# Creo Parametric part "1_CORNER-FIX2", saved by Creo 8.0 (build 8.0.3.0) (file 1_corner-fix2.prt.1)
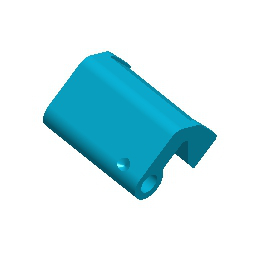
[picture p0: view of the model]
Units: millimeter Newton Second (mmNs); MM, TONNE, SECS

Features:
  1. datum plane "RIGHT"
  2. datum plane "TOP"
  3. datum plane "FRONT"
  4. coordinate system
  5. protrusion
  6. cut
  7. cut
  8. datum plane "DTM1"
  9. cut
  10. cut
  11. cut

Layers: 0_ALL_AXIS, 0_ALL_CSYS, 0_ALL_CURVES, 0_ALL_PLANES, 0_ALL_POINTS, 0_ALL_SURFS, LIBIQIANG

Surfaces: 13 plane, 13 cylinder, 2 cone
